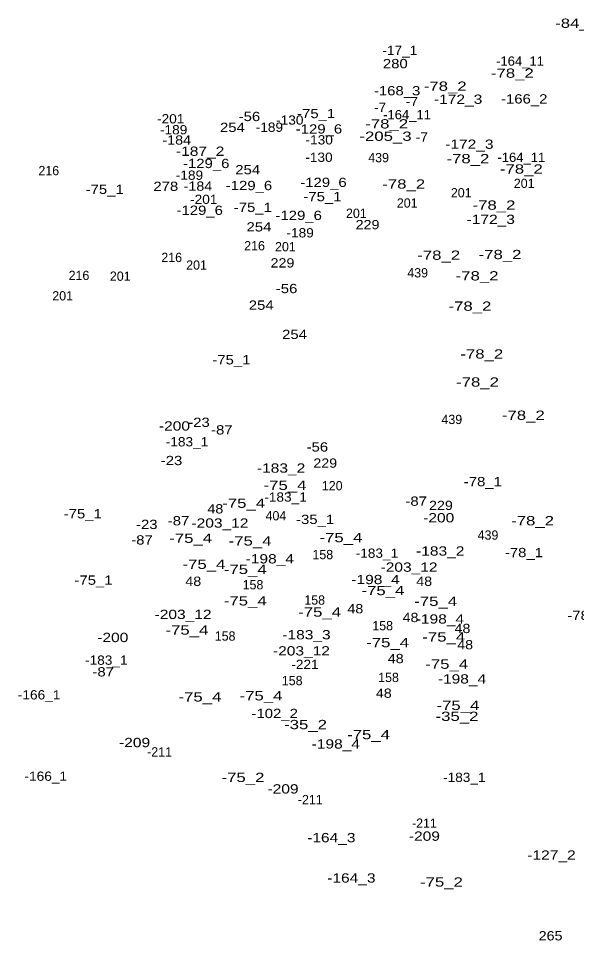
# Model space of a CAD drawing. Extents: x -658110 to -655750, y -1000429 to -997657.
# Drawn here: x -657540.3 to -657300, y -998728.2 to -998330.8 of the extents above; entities that cross this region are included whole.
import ezdxf
from ezdxf.enums import TextEntityAlignment as Align

# ---------------------------------------------------------------- set-up
doc = ezdxf.new("R2010")
doc.units = 0
doc.header["$LTSCALE"] = 1.6
doc.layers.add('24', color=7, linetype='Continuous')

msp = doc.modelspace()

# ---------------------------------------------------------------- texts
at = {"layer": '24'}
for s, width, p in [('-84_3', 1.35, (-657299.94, -998334.85)), ('-17_1', 1.1, (-657376.081, -998346.53)), ('280', 1.2, (-657378.02, -998352.25)), ('-164_11', 1.05, (-657324.321, -998351.15)), ('-78_2', 1.35, (-657327.62, -998356.37)), ('-168_3', 1.2, (-657377.25, -998363.93)), ('-78_2', 1.35, (-657356.54, -998361.98)), ('-7', 1.1, (-657370.861, -998368.58)), ('-172_3', 1.25, (-657350.97, -998367.6)), ('-166_2', 1.2, (-657322.5, -998367.46)), ('-7', 1.1, (-657384.611, -998371.12)), ('-201', 1.1, (-657474.76, -998376.04)), ('-56', 1.2, (-657440.84, -998375.04)), ('-130', 1.1, (-657423.471, -998376.58)), ('-75_1', 1.2, (-657412.11, -998373.76)), ('-164_11', 1.05, (-657372.971, -998374.25)), ('-189', 1.1, (-657473.49, -998380.76)), ('254', 1.2, (-657448.189, -998379.75)), ('-189', 1.1, (-657432.26, -998379.67)), ('-129_6', 1.2, (-657410.9, -998380.41)), ('-78_2', 1.35, (-657381.74, -998378.22)), ('-184', 1.15, (-657472.15, -998385.18)), ('-130', 1.1, (-657410.801, -998385.11)), ('-205_3', 1.35, (-657382.24, -998383.55)), ('-7', 1.1, (-657366.601, -998383.9)), ('-172_3', 1.25, (-657346.13, -998386.99)), ('-187_2', 1.25, (-657462.08, -998390.01)), ('-130', 1.1, (-657410.9, -998392.62)), ('-78_2', 1.35, (-657346.77, -998393.22)), ('-164_11', 1.05, (-657323.74, -998392.64)), ('-129_6', 1.2, (-657459.47, -998395.29)), ('-189', 1.1, (-657466.68, -998400.35)), ('254', 1.2, (-657441.6, -998397.98)), ('-78_2', 1.35, (-657323.75, -998397.67)), ('278', 1.2, (-657476.87, -998405.14)), ('-184', 1.15, (-657463.03, -998405.06)), ('-129_6', 1.2, (-657441.04, -998404.8)), ('-129_6', 1.2, (-657408.97, -998403.45)), ('-78_2', 1.35, (-657374.42, -998404.15)), ('-75_1', 1.2, (-657503.19, -998406.45)), ('-201', 1.1, (-657460.51, -998410.75)), ('-75_1', 1.2, (-657409.4, -998409.56)), ('-129_6', 1.2, (-657462.26, -998415.46)), ('-75_1', 1.2, (-657439.37, -998414.2)), ('-78_2', 1.35, (-657335.55, -998413.25)), ('-129_6', 1.2, (-657419.63, -998417.67)), ('-172_3', 1.25, (-657336.93, -998419.37)), ('254', 1.2, (-657436.75, -998422.62)), ('229', 1.15, (-657389.98, -998421.65)), ('-189', 1.1, (-657419.01, -998425.18)), ('-78_2', 1.35, (-657359.34, -998434.83)), ('-78_2', 1.35, (-657332.94, -998434.54)), ('229', 1.15, (-657426.62, -998438.14)), ('-78_2', 1.35, (-657342.81, -998443.73)), ('-56', 1.2, (-657424.85, -998449.19)), ('254', 1.2, (-657435.78, -998456.36)), ('-78_2', 1.35, (-657345.9, -998456.79)), ('254', 1.2, (-657421.429, -998468.97)), ('-75_1', 1.2, (-657448.62, -998479.92)), ('-78_2', 1.35, (-657340.78, -998477.4)), ('-78_2', 1.35, (-657342.62, -998489.49)), ('-78_2', 1.35, (-657322.89, -998503.81)), ('-200', 1.25, (-657473.14, -998508.43)), ('-23', 1.2, (-657462.57, -998506.85)), ('-87', 1.2, (-657452.74, -998510.11)), ('-183_1', 1.1, (-657467.73, -998515.25)), ('-56', 1.2, (-657411.59, -998517.48)), ('-23', 1.2, (-657474.4, -998523.33)), ('229', 1.15, (-657408.21, -998524.44)), ('-183_2', 1.25, (-657427.22, -998526.58)), ('-78_1', 1.2, (-657340.32, -998532.42)), ('-75_4', 1.35, (-657425.52, -998533.99)), ('-183_1', 1.1, (-657425.299, -998539.07)), ('48', 1.15, (-657455.54, -998544.15)), ('-75_4', 1.35, (-657443.319, -998541.72)), ('-87', 1.2, (-657369.03, -998540.84)), ('229', 1.15, (-657358.38, -998542.67)), ('-75_1', 1.2, (-657512.63, -998546.28)), ('-200', 1.25, (-657359.341, -998548)), ('-23', 1.2, (-657485.06, -998550.87)), ('-87', 1.2, (-657471.37, -998549.29)), ('-203_12', 1.25, (-657453.54, -998550.27)), ('-35_1', 1.2, (-657412.569, -998548.71)), ('-78_2', 1.35, (-657318.92, -998549.27)), ('-87', 1.2, (-657487.111, -998557.55)), ('-75_4', 1.35, (-657466.14, -998556.81)), ('-75_4', 1.35, (-657440.569, -998557.99)), ('-75_4', 1.35, (-657401.449, -998556.53)), ('-183_1', 1.1, (-657385.939, -998563.27)), ('-183_2', 1.25, (-657358.669, -998562.31)), ('-78_1', 1.2, (-657322.63, -998562.99)), ('-75_4', 1.35, (-657460.429, -998568.04)), ('-198_4', 1.25, (-657432.08, -998565.69)), ('-75_4', 1.35, (-657442.64, -998570.26)), ('-203_12', 1.25, (-657372.11, -998569.28)), ('-75_1', 1.2, (-657507.99, -998574.89)), ('48', 1.15, (-657465.04, -998575.37)), ('-198_4', 1.25, (-657386.56, -998574.62)), ('48', 1.15, (-657365.59, -998575.37)), ('-75_4', 1.35, (-657383.36, -998579.36)), ('-75_4', 1.35, (-657442.64, -998583.8)), ('-75_4', 1.35, (-657360.64, -998584)), ('48', 1.15, (-657395.25, -998587.2)), ('-203_12', 1.25, (-657469.429, -998589.65)), ('-75_4', 1.35, (-657410.63, -998588.64)), ('48', 1.15, (-657371.47, -998590.98)), ('-198_4', 1.25, (-657358.81, -998591.62)), ('-78_1', 1.2, (-657295.75, -998590.08)), ('48', 1.15, (-657349.1, -998595.72)), ('-200', 1.25, (-657499.701, -998599.59)), ('-75_4', 1.35, (-657467.78, -998596.39)), ('-183_3', 1.25, (-657416.28, -998598.41)), ('-75_4', 1.35, (-657357.16, -998599.37)), ('-75_4', 1.35, (-657381.329, -998601.8)), ('48', 1.15, (-657347.939, -998602.71)), ('-203_12', 1.25, (-657418.449, -998605.36)), ('-183_1', 1.1, (-657502.49, -998609.37)), ('-221', 1.1, (-657416.931, -998611.2)), ('48', 1.15, (-657377.84, -998608.68)), ('-75_4', 1.35, (-657355.9, -998611.09)), ('-87', 1.2, (-657503.821, -998614.41)), ('-198_4', 1.25, (-657349.31, -998617.46)), ('48', 1.15, (-657382.98, -998623.61)), ('-166_1', 1.1, (-657531.42, -998624.32)), ('-75_4', 1.35, (-657462.169, -998625.21)), ('-75_4', 1.35, (-657435.87, -998624.73)), ('-75_4', 1.35, (-657351.069, -998628.89)), ('-102_2', 1.2, (-657429.97, -998632.35)), ('-35_2', 1.35, (-657351.459, -998633.56)), ('-35_2', 1.35, (-657416.679, -998637.13)), ('-75_4', 1.35, (-657389.549, -998641.46)), ('-209', 1.25, (-657490.31, -998644.88)), ('-198_4', 1.25, (-657403.65, -998645.49)), ('-166_1', 1.1, (-657528.55, -998659.39)), ('-75_2', 1.35, (-657443.64, -998659.91)), ('-183_1', 1.1, (-657348.309, -998659.88)), ('-209', 1.25, (-657426.37, -998664.86)), ('-164_3', 1.25, (-657405.58, -998685.86)), ('-209', 1.25, (-657365.5, -998685.22)), ('-127_2', 1.25, (-657310.76, -998693.37)), ('-164_3', 1.25, (-657396.94, -998703.25)), ('-75_2', 1.35, (-657358.15, -998705)), ('265', 1.15, (-657311.15, -998728.18))]:
    msp.add_text(s, height=4, dxfattribs=dict(at, width=width)).set_placement(p, align=Align.CENTER)
for s, p in [('439', (-657385.217, -998392.78)), ('216', (-657527.25, -998398.36)), ('201', (-657322.52, -998403.87)), ('201', (-657349.63, -998407.91)), ('201', (-657372.89, -998412.33)), ('201', (-657394.8, -998416.76)), ('216', (-657438.65, -998430.75)), ('201', (-657425.36, -998431.18)), ('216', (-657474.321, -998435.79)), ('201', (-657463.62, -998439.07)), ('216', (-657514.26, -998443.55)), ('201', (-657496.49, -998443.88)), ('439', (-657368.397, -998442.42)), ('201', (-657521.29, -998452.34)), ('439', (-657353.687, -998505.61)), ('120', (-657405.19, -998534.17)), ('404', (-657429.44, -998547.14)), ('439', (-657338.107, -998555.46)), ('158', (-657409.26, -998563.87)), ('158', (-657439.309, -998576.87)), ('158', (-657412.75, -998583.46)), ('158', (-657383.47, -998594.52)), ('158', (-657451.329, -998598.98)), ('158', (-657422.439, -998618.18)), ('158', (-657380.949, -998616.82)), ('-211', (-657479.541, -998648.91)), ('-211', (-657414.64, -998669.47)), ('-211', (-657365.49, -998679.65))]:
    msp.add_text(s, height=4, dxfattribs=at).set_placement(p, align=Align.CENTER)

doc.saveas('drawing.dxf')
